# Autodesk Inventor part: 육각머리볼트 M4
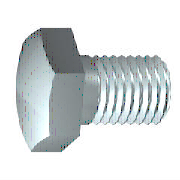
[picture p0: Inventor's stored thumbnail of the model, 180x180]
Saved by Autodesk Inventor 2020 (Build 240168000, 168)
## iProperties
Created: 2012-02
Part Number: 육각머리볼트 M4
Material: 스테인리스강
Description: 6각 머리 나사
Document SubType Name: Modeling
Standard: ISO 4017
Designer: mduedu
Standard Revision: Third edition 1999-08-15
Standards Organization: ISO
Language: ko-KR
Size Designation: M4 x 10
Categories: <MemberInstance><Categories><Category DisplayName="조임쇠" InternalName="e4da775c-781d-43d5-af7c-5136215cf5a6" Mnemonic="FSTN"><Category DisplayName="볼트" InternalN
Density: 8.08 g/cm^3
Appearance: 반광택
IsCustomPart: 0
Author: mduedu
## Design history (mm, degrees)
sketch "스케치1"
  geometry: L1 (0, 3.015)-(0, 2); L2 (1.75, 2)-(10, 2); L3 (10, 2)-(10, 0); L4 (10, 0)-(-0.4, 0); L5 (-2.48, 0)-(12.08, 0) reference; L6 (-0.4, 0)-(-0.4, 3.015); L7 (-0.4, 3.015)-(0, 3.015); L8 (1.75, 2)-(1.32, 2); L9 (1.32, 2)-(0, 2); L10 (0, -0.603)-(0, 3.618) reference
  constraints: 16 end point, 2 collinear, 2 perpendicular, 1 parallel
  dimensions: "d0" = 10 distance between parallel lines of L3 L1 (= NLG); "d1" = 8.25 distance from line of L2.start L3 (= GEL); "d2" = 4 diameter of L2 L4 (= GD); "d9" = 0.4001 distance between parallel lines of L6 L1 (computed from SD); "d10" = 6.03 diameter of L7 L4 (= SD2); "d13" = 0.42952 distance of L2.start L8.end (computed from GAL); "d14" = 4 diameter of L9 L4 (= BDM)
revolve "본체" sketch "스케치1" stored, may be unused: angle "d12" = 90 deg
sketch "스케치2"
  geometry: L1 (0, 4.041)-(3.5, 2.021); L2 (3.5, 2.021)-(3.5, -2.021); L3 (3.5, -2.021)-(0, -4.041); L4 (0, -4.041)-(-3.5, -2.021); L5 (-3.5, -2.021)-(-3.5, 2.021); L6 (-3.5, 2.021)-(0, 4.041); 2 further points
  constraints: 12 end point, 1 coincident, 1 vertical, 11 other
  dimensions: "d11" = 7 distance between parallel lines of L5 L2 (= SW)
extrude "머리" join sketch "스케치2" distance "d3" = 2.4 (= KOH - SD); taper "d4" = 0 deg
sketch "스케치4"
  geometry: L1 (-2.8, 3.5)-(-2.8, 4.041); L2 (-2.8, 4.041)-(-2.487, 4.041); L3 (-2.487, 4.041)-(-2.8, 3.5); L4 (-3.28, 0)-(0.08, 0) reference; L5 (-0.4, 4.041)-(-2.8, 4.041) reference; L6 (-2.8, 2.021)-(-2.8, 4.041) reference
  constraints: 6 end point, 2 collinear, 1 perpendicular, 1 vertical
  dimensions: "d5" = 30 deg angle of L3 L1 (= ANG1); "d19" = 7 diameter of L1.start L4 (= SW0)
revolve "모따기1" sketch "스케치4" stored, may be unused: angle "d21" = 90 deg
workplane "Work Plane1"
body "Solid1"
feature "스레드" dims "d15" = 8.25 (= GEL), "d16" = 0
chamfer "모따기2" distance "d6" = 0.42941 (= -0.5 x SPD + 0.5 x GD); stored, may be unused: second distance "d7" = 0.42952 (computed from GUL), angle "d55" = 45 deg
other parameters: "NLG" = 10 [user parameter; used in 1 equation term], "GD" = 4 (= NND) [user parameter; used in 2 equation terms], "BDM" = 4 (= NND) [user parameter; used in 1 equation term], "KOH" = 2.8 [user parameter; used in 1 equation term], "GEL" = 8.25 [user parameter; used in 2 equation terms], "SW" = 7 [user parameter; used in 2 equation terms], "SW0" = 7 (= SW) [user parameter; used in 1 equation term], "SPD" = 3.14117 (= NND - 1.2269 x PTC) [user parameter; used in 1 equation term], "SD2" = 6.03 [user parameter; used in 2 equation terms], "SD" = 0.4 [user parameter; used in 2 equation terms], "ANG1" = 30 deg [user parameter; used in 1 equation term], "GAL" = 0.42941 (= 0.61345 x PTC) [user parameter; used in 1 equation term], "GUL" = 0.42941 (= 0.61345 x PTC) [user parameter; used in 1 equation term], "d8" = 0, "RR" = 0.2 [user parameter], "d57" = 0, "d58" = 0, "TPU" = 14.28571 (computed from PTC) [user parameter], "GD1" = 3.14117 (= THREADDIA - 1.2269 x PTC) [user parameter], "THREADDIA" = 4 [user parameter; used in 1 equation term], "SDH" = 6.03 (= SD2) [user parameter], "SDHG" = 2.1 [user parameter], "TOA" = 30 deg [user parameter], "PTC" = 0.7 [user parameter; used in 5 equation terms], "NND" = 4 [user parameter; used in 3 equation terms], "E0" = 8.085 [user parameter]
